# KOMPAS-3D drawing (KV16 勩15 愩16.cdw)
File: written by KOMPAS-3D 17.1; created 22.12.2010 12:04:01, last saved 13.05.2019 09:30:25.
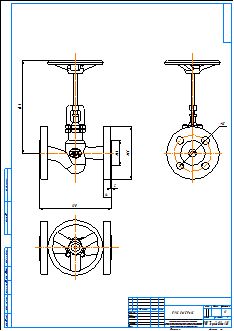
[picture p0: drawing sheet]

Title block, sheet 1: name: KV16 Ду15 Ру16; material: Внимание! Данный продукт является объектом авторского права ООО «Торговый Дом АДЛ». / Запрещается изменение, копирование, распространение / (в том числе путем копирования на другие сайты и ресурсы в Интернете) / или любое иное использование информации и объектов без предварительного / согласия правообладателя (ООО «Торговый Дом АДЛ»).; scale: 1:1; sheets: 1; organisation: ООО "Торговый дом АДЛ"; sheet format: A2; stored path: \\adlc.lan\data\АДЛ_ПКД\3D-модели\ADL production\Вентили ГРАНВЕНТ\KV16\KOMPAS 2D\KV16 Ду15 Ру16.cdw

Views: Спереди 1, Проекционный вид 3, Вид 6
Dimensions and other numbers on the sheet: 46; 95; 65; 130; 2; 14; 167; 1:1; 1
